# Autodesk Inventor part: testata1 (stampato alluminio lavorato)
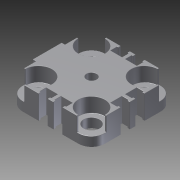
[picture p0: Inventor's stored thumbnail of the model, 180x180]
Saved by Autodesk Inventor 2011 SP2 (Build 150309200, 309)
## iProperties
Created: 2018-03
Part Number: testata1 (stampato alluminio lavorato)
Document SubType Name: Modeling
Designer: 18619647
Density: 1 g/cm^3
Author: 18619647
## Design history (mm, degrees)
sketch "Schizzo1"
  geometry: L1 (0, 0)-(25, 0); L2 (25, 0)-(25, 25); L3 (25, 25)-(-25, 25); L4 (-25, 25)-(-25, -25); L5 (-25, -25)-(25, -25); L6 (25, -25)-(25, 0); C1 r 15.75 at (0, 0); 1 further point
  constraints: 12 end point, 2 parallel, 2 perpendicular, 1 centre point, 1 coincident, 1 horizontal
  dimensions: "d0" = 31.5 diameter of C1; "d1" = 25 distance of L1.start L1.end; "d2" = 25 distance of L1.end L2.end; "d3" = 50 distance of L2.end L3.end; "d4" = 50 distance of L3.end L4.end; "d5" = 50 distance of L4.end L5.end
extrude "Estrusione1" new body sketch "Schizzo1" distance "d6" = 14.4; taper "d7" = 0 deg
fillet "Raccordo1" dims "d8" = 8
sketch "Schizzo2"
  geometry: L1 (-25, -17)-(-25, 17) reference; L2 (-17, 25)-(17, 25) reference; L3 (-25, 0)-(-27, 0); L4 (-27, 0)-(-27, -8.8); L5 (-27, -8.8)-(-25, -8.8); L6 (-25, -8.8)-(-25, 8.8); L7 (-25, 8.8)-(-27, 8.8); L8 (-27, 8.8)-(-27, 0)
  constraints: 12 end point, 2 parallel, 2 perpendicular, 2 point on line, 1 midpoint
  dimensions: "d9" = 2 distance of L3.start L3.end; "d10" = 8.8 distance of L3.end L4.end; "d11" = 2 distance of L4.end L5.end; "d12" = 17.6 distance of L5.end L6.end
extrude "Estrusione2" join sketch "Schizzo2" distance "d13" = 14.4; taper "d14" = 0 deg
hole "Hole1" diameter "d17" = 9.5; stored, may be unused: countersink angle "d21" = 82 deg, drill point angle "d23" = 118 deg; dims "d15" = 8.9, "d16" = 8.9, "d18" = 6, "d19" = 3.023, "d20" = 2, "d22" = 8.2
node "Piano di lavoro1"
sketch "Schizzo3"
  geometry: L1 (1.75, -25)-(1.75, -23.5); L2 (1.75, -23.5)-(1, -23.5); L3 (1, -23.5)-(1, -19.5); L4 (1, -19.5)-(8, -19.5); L5 (8, -19.5)-(8, -23.5); L6 (8, -23.5)-(7.25, -23.5); L7 (7.25, -23.5)-(7.25, -25); L8 (-1, -19.5)-(-8, -19.5); L9 (-1, -23.5)-(-1, -19.5); L10 (-1.75, -23.5)-(-1, -23.5); L11 (-1.75, -25)-(-1.75, -23.5); L12 (-8, -19.5)-(-8, -23.5); L13 (-8, -23.5)-(-7.25, -23.5); L14 (-7.25, -23.5)-(-7.25, -25); L15 (-17, 25)-(17, 25) reference; L16 (25, 17)-(25, 8.8) reference; L17 (17, -25)-(-17, -25) reference; L18 (-25, -17)-(-25, 17) reference; L19 (7.25, -25)-(1.75, -25); L20 (-1.75, -25)-(-7.25, -25); L21 (25, 8.8)-(27, 8.8) reference; L22 (27, 8.8)-(27, -8.8) reference; L23 (27, -8.8)-(25, -8.8) reference; L24 (25, -8.8)-(25, -17) reference; C1 r 4.75 at (16.1, -16.1) reference; A1 r 8 centre (-17, 17) between (-17, 25) and (-25, 17) reference; A2 r 8 centre (17, 17) between (25, 17) and (17, 25) reference; A3 r 8 centre (17, -17) between (17, -25) and (25, -17) reference; A4 r 8 centre (-17, -17) between (-25, -17) and (-17, -25) reference
  constraints: 32 end point, 2 collinear, 1 parallel, 1 perpendicular
  dimensions: "d30" = 1.5 distance of L1.start L1.end; "d31" = 0.75 distance of L1.end L2.end; "d32" = 4 distance of L2.end L3.end; "d33" = 7 distance of L3.end L4.end; "d34" = 4 distance of L4.end L5.end; "d35" = 0.75 distance of L5.end L6.end
extrude "Estrusione3" cut sketch "Schizzo3" distance "d36" = 56; taper "d37" = 0 deg
pattern_circular "Serie circolare1" dims angle "d39" = 180 deg
pattern_linear "Serie rettangolare1" dims "d43" = 32.2, "d46" = 32.2
sketch "Schizzo5"
  geometry: C1 r 16 at (0, 0); 1 further point
  constraints: 1 centre point, 1 coincident
  dimensions: "d64" = 32 diameter of C1
extrude "Estrusione4" join sketch "Schizzo5" distance "d65" = 0.8; taper "d66" = 0 deg
sketch "Schizzo6"
  geometry: C1 r 16 at (0, 0) reference; C2 r 17.5 at (0, 0); C3 r 16 at (0, 0)
  constraints: 2 centre point, 2 coincident
  dimensions: "d67" = 35 diameter of C2; "d68" = 32 diameter of C3
extrude "Estrusione5" cut sketch "Schizzo6" distance "d69" = 0.7; taper "d70" = 0 deg
sketch "Schizzo7"
  geometry: C1 r 16 at (0, 0) reference; C2 r 10.5 at (0, 0)
  constraints: 1 centre point, 1 coincident
  dimensions: "d71" = 21 diameter of C2
extrude "Estrusione6" cut sketch "Schizzo7" distance "d72" = 4; taper "d73" = 0 deg
sketch "Schizzo9"
  geometry: L1 (0, 0)-(14, 0); C1 r 16 at (0, 0) reference
  constraints: 2 end point, 1 horizontal
  dimensions: "d77" = 14 distance of L1.start L1.end
hole "Hole3" sketch "Schizzo9" at (14, 0) diameter "d78" = 2; stored, may be unused: countersink angle "d82" = 90 deg, drill point angle "d84" = 0 deg; dims "d79" = 6, "d80" = 4, "d81" = 2, "d83" = 8
hole "Hole4" diameter "d87" = 7.5; stored, may be unused: countersink angle "d91" = 90 deg, drill point angle "d93" = 0 deg; dims "d85" = 7.2, "d86" = 8.8, "d88" = 6, "d89" = 4, "d90" = 2, "d92" = 14
sketch "Schizzo10"
  geometry: C1 r 3.75 at (-7.2, 8.8) reference; C2 r 4.1 at (-7.2, 8.8); 1 further point
  constraints: 1 centre point, 1 coincident
  dimensions: "d94" = 8.2 diameter of C2
extrude "Estrusione8" cut sketch "Schizzo10" distance "d95" = 12; taper "d96" = 0 deg
sketch "Schizzo11"
  geometry: C1 r 4.1 at (-7.2, 8.8) reference; C2 r 4.5 at (-7.2, 8.8); 1 further point
  constraints: 1 centre point, 1 coincident
  dimensions: "d97" = 9 diameter of C2
extrude "Estrusione9" cut sketch "Schizzo11" distance "d98" = 12; taper "d99" = 0 deg
feature "Filettatura7" dims "d100" = 10, "d101" = 2
chamfer "Smusso1" distance "d102" = 0.5; stored, may be unused: second distance "d103" = 2, angle "d104" = 45 deg
sketch "Schizzo12"
  geometry: C1 r 10.5 at (0, 0) reference; C2 r 8.25 at (0, 0)
  constraints: 1 centre point, 1 coincident
  dimensions: "d105" = 16.5 diameter of C2
extrude "Estrusione10" cut sketch "Schizzo12" distance "d106" = 4; taper "d107" = 0 deg
pattern_circular "Serie circolare2" dims angle "d109" = 180 deg
sketch "Schizzo13"
  geometry: L1 (-25, -17)-(-25, -8.8) reference; L2 (-8, 23.5)-(-7.25, 23.5) reference; L3 (-16.1, -24.1)-(-16.1, -28.112); L4 (-16.1, -28.112)-(-34.474, -28.112); L5 (-34.474, -28.112)-(-30.523, -16.1); L6 (-30.523, -16.1)-(-24.1, -16.1); C1 r 4.75 at (-16.1, -16.1) reference; A1 r 8 centre (-16.1, -16.1) between (-16.1, -24.1) and (-24.1, -16.1); 1 further point
  constraints: 8 end point, 3 perpendicular, 2 point on circle, 1 centre point, 1 coincident
  dimensions: "d111" = 16 diameter of A1
extrude "Estrusione11" cut sketch "Schizzo13" distance "d112" = 8.8; taper "d113" = 0 deg
mirror "Specchio2"
mirror "Specchio3"
fillet "Raccordo2" dims "d114" = 0.2
sketch "Schizzo14"
  geometry: C1 r 3 at (0, 0); 1 further point
  constraints: 1 centre point, 1 coincident
  dimensions: "d115" = 6 diameter of C1
extrude "Estrusione12" cut sketch "Schizzo14" distance "d116" = 4.5; taper "d117" = 0 deg
fillet "Raccordo3" dims "d118" = 0.2
sketch "Schizzo15"
  geometry: L1 (26.5, 2.7)-(27, 2.2) reference; L2 (27, 2.2)-(27, 0) reference; L3 (27, 0)-(17.5, 0) reference; L4 (17.5, 0)-(17.5, 0.7) reference; L5 (17.5, 0.7)-(16, 0.7) reference; L6 (16, 0.7)-(16, -0.8) reference; L7 (16, -0.8)-(15, -0.8) reference; L8 (15, -0.8)-(15, 2.7) reference; L9 (15, 3.45)-(15, 2.7) reference; L10 (15, 2.7)-(26.5, 2.7) reference; L11 (10.5, -0.8)-(10.5, 3.2) reference; L12 (10.5, 3.2)-(8.25, 3.2) reference; L13 (8.25, 3.2)-(8.25, 7.2) reference; L14 (8.25, 7.2)-(-8.25, 7.2) reference; L15 (-8.25, 7.2)-(-8.25, 3.2) reference; L16 (-8.25, 3.2)-(-10.5, 3.2) reference; L17 (-10.5, 3.2)-(-10.5, -0.8) reference; L18 (-10.5, -0.8)-(-16, -0.8) reference; L19 (-16, -0.8)-(-16, 0.7) reference; L20 (-16, 0.7)-(-17.5, 0.7) reference; L21 (-17.5, 0.7)-(-17.5, 0) reference; L22 (-17.5, 0)-(-25, 0) reference; L23 (-25, 0)-(-25, 14.2) reference; L24 (-24.8, 14.4)-(-3.2, 14.4) reference; L25 (-3, 14.2)-(-3, 10.1) reference; L26 (-2.8, 9.9)-(2.8, 9.9) reference; L27 (3, 10.1)-(3, 14.2) reference; L28 (3.2, 14.4)-(26.8, 14.4) reference; L29 (27, 14.2)-(27, 12.2) reference; L30 (27, 12.2)-(26.5, 11.7) reference; L31 (26.5, 11.7)-(15, 11.7) reference; L32 (15, 11.7)-(15, 10.95) reference; L33 (15, 10.95)-(13, 10.95) reference; L34 (13, 10.95)-(13, 3.45) reference; L35 (13, 3.45)-(13, -0.8) reference; L36 (13, -0.8)-(10.5, -0.8) reference; A1 r 0.2 centre (-24.8, 14.2) between (-24.8, 14.4) and (-25, 14.2) reference; A2 r 0.2 centre (-3.2, 14.2) between (-3, 14.2) and (-3.2, 14.4) reference; A3 r 0.2 centre (-2.8, 10.1) between (-3, 10.1) and (-2.8, 9.9) reference; A4 r 0.2 centre (2.8, 10.1) between (2.8, 9.9) and (3, 10.1) reference; A5 r 0.2 centre (3.2, 14.2) between (3.2, 14.4) and (3, 14.2) reference; A6 r 0.2 centre (26.8, 14.2) between (27, 14.2) and (26.8, 14.4) reference; 1 further point
  node "Proietta spigoli di taglio2"
node "Solido1"
node "Piano di lavoro2"
node "Proietta spigoli di taglio1"
other parameters: "d28" = 28
